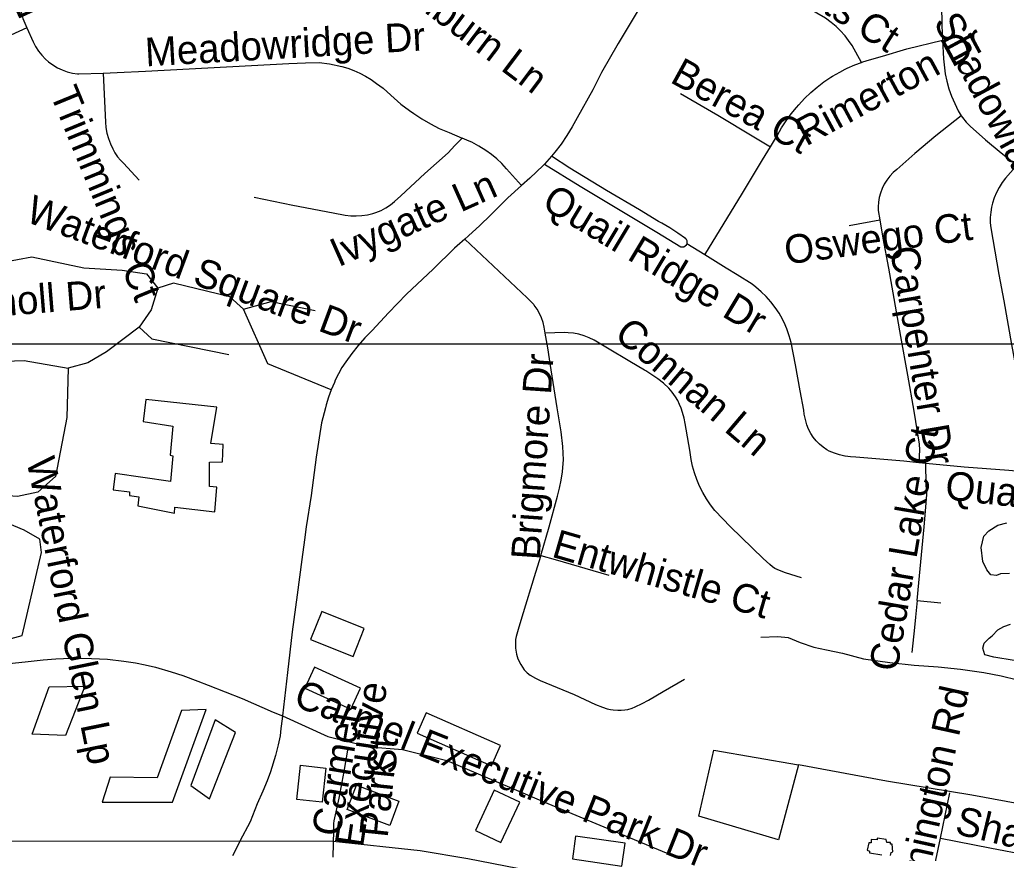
# Model space of a CAD drawing. Extents: x 1383679 to 1536984, y 460658 to 651027.
# Drawn here: x 1447333 to 1450610, y 491982 to 494749 of the extents above; entities that cross this region are included whole.
import ezdxf

# ---------------------------------------------------------------- set-up
doc = ezdxf.new("R2010")
doc.units = 0
for name, color, linetype in [('Exist Cultural Warehouse Building Footprint', 7, 'Continuous'), ('Exist Hydrographic Misc Water Feature', 7, 'Continuous'), ('Exist Road Non-System Type 51', 7, 'Continuous'), ('Exist Road Non-System Type 51 Label', 7, 'Continuous'), ('Exist Road Primary NC UnDivided 4 Lane Attributed', 7, 'Continuous'), ('Exist Utilities Electrical Transmission Line', 7, 'Continuous'), ('Map Preparation Inset Cut Line', 7, 'Continuous')]:
    doc.layers.add(name, color=color, linetype=linetype)

msp = doc.modelspace()

# ---------------------------------------------------------------- linework, layer by layer
at = {"layer": 'Exist Cultural Warehouse Building Footprint'}
for points in [[(1447752.1, 493487.8), (1447742.5, 493414.9), (1447841.8, 493399.4), (1447832.2, 493303.1), (1447841.8, 493301.5), (1447833.8, 493216.2), (1447649.7, 493242.6), (1447643.3, 493188.2), (1447697.7, 493182), (1447697.7, 493169.6), (1447728.1, 493164.9), (1447724.9, 493135.4), (1447846.6, 493110.6), (1447848.2, 493130.8), (1447981, 493115.2), (1447987.4, 493197.5), (1447963.4, 493199.1), (1447963.4, 493279.8), (1448006.6, 493281.4), (1448008.2, 493338.8), (1447968.2, 493341.9), (1447987.4, 493463), (1447752.1, 493487.8)], [(1448336.3, 492784.6), (1448299.3, 492691.6), (1448440.3, 492635.5), (1448477.3, 492728.5), (1448336.3, 492784.6)], [(1448312.3, 492599.8), (1448280.2, 492529.8), (1448432.3, 492460.1), (1448464.4, 492530.1), (1448312.3, 492599.8)], [(1447430.4, 492533.8), (1447548.9, 492536.9), (1447484.9, 492372.4), (1447374.4, 492377), (1447430.4, 492533.8)], [(1447633.7, 492234.2), (1447606.5, 492151.9), (1447840.2, 492151.9), (1447952.2, 492459.3), (1447870.6, 492456.2), (1447788.9, 492232.6), (1447633.7, 492234.2)], [(1448683.6, 492448.4), (1448653.5, 492380.2), (1448899.7, 492271.5), (1448929.8, 492339.7), (1448683.6, 492448.4)], [(1447982.6, 492425.2), (1447901, 492206.2), (1447963.4, 492162.8), (1448049.8, 492383.2), (1447982.6, 492425.2)], [(1448265.9, 492273.8), (1448350.1, 492264.7), (1448337.9, 492151.1), (1448253.6, 492160.2), (1448265.9, 492273.8)], [(1448592.4, 492155), (1448562.1, 492074.2), (1448421.1, 492127.1), (1448451.4, 492207.9), (1448592.4, 492155)], [(1448846.8, 492057.2), (1448931.5, 492017.7), (1448994.1, 492151.9), (1448909.4, 492191.4), (1448846.8, 492057.2)], [(1449179.7, 492038.6), (1449168.9, 491962.9), (1449333.4, 491939.2), (1449344.3, 492014.9), (1449179.7, 492038.6)], [(1450161.1, 492027.9), (1450162.1, 492016), (1450153.9, 492016), (1450148.8, 491992.2), (1450156, 491989.2), (1450156, 491983.2), (1450196.9, 491976.3)], [(1450225.5, 491974.3), (1450227.5, 491984.2), (1450233.7, 491986.2), (1450231.6, 492012), (1450225.5, 492012), (1450225.5, 492017.9), (1450213.2, 492017.9), (1450211.2, 492027.9), (1450181.5, 492031.8), (1450181.5, 492025.9), (1450161.1, 492027.9)]]:
    msp.add_lwpolyline(points, dxfattribs=at)
at = {"layer": 'Exist Hydrographic Misc Water Feature'}
for points in [[(1450621.7, 492911.1), (1450591.8, 492909.2), (1450577.6, 492903.8), (1450559.6, 492905.8), (1450545.9, 492922.4), (1450532.4, 492950.6), (1450527.3, 492996.7), (1450536, 493034.3), (1450552.3, 493052), (1450582.6, 493071.1), (1450612.8, 493078.7)], [(1450704.3, 492610.7), (1450568.6, 492633.2), (1450538.7, 492640.3), (1450533.1, 492662.6), (1450537.4, 492679.8), (1450553.8, 492695.8), (1450563.9, 492703.8), (1450582.2, 492723.1), (1450602.4, 492735.1), (1450624.7, 492742.8)], [(1449795.5, 492699.6), (1449851.5, 492700.9), (1449885.4, 492697.8), (1449925.2, 492681.4), (1449971, 492666.5), (1450012.9, 492657.5), (1450066.7, 492646.5), (1450136.3, 492627.1), (1450224.1, 492615.5), (1450304.1, 492606.5), (1450383.9, 492600.8), (1450457.9, 492593.5), (1450535.7, 492582.1), (1450593.5, 492571.1), (1450647.3, 492557.7), (1450703, 492542.6)]]:
    msp.add_lwpolyline(points, dxfattribs=at)
at = {"layer": 'Exist Road Non-System Type 51'}
for p, q in [((1449099.6, 494296.2), (1449076.3, 494270)), ((1450089, 494065.6), (1450190.4, 494084.8)), ((1449608.8, 493968.2), (1449549.4, 494005)), ((1450343, 493276.3), (1450319.5, 493278.5)), ((1450314.4, 492821), (1450392.7, 492813.5)), ((1450392, 492032.4), (1450423.4, 492182.8)), ((1448098.2, 492085.7), (1448064.5, 492021.5)), ((1448064.5, 492021.5), (1448050.4, 491994.5)), ((1450365.6, 491906.1), (1450392, 492032.4)), ((1448050.4, 491994.5), (1448039.3, 491973.3))]:
    msp.add_line(p, q, dxfattribs=at)
for points in [[(1447447, 495029.8), (1447430.6, 495001.9), (1447397.6, 494952.2), (1447356, 494884.3), (1447348.4, 494870.7), (1447342.1, 494855.8), (1447337.5, 494840.3), (1447334.6, 494824.3), (1447333.5, 494808.2), (1447334.1, 494792.3), (1447335.1, 494784.2), (1447342.8, 494753.8), (1447356.7, 494722.8)], [(1450128.9, 494607.2), (1450098.1, 494663.3), (1450086.6, 494680.7), (1450075, 494695.8), (1450074, 494697.2), (1450060.1, 494712.6), (1450045, 494727), (1450028.9, 494740.2), (1450009.5, 494753.9), (1449989.2, 494766.3), (1449987, 494767.6), (1449919.7, 494807.5), (1449857, 494844.9), (1449759.9, 494904)], [(1450385, 494889.7), (1450389.1, 494871), (1450392.8, 494847.4), (1450394.9, 494823.5), (1450395.4, 494799.6), (1450396.4, 494729.7), (1450398.6, 494681.4)], [(1449408.7, 494816.6), (1449400.6, 494802.9), (1449320.9, 494670.4), (1449265.1, 494573.9), (1449236.3, 494516.5), (1449184.6, 494423.7), (1449168.1, 494393.8), (1449150.3, 494364.8), (1449131.1, 494336.5), (1449110.6, 494309.2), (1449105.5, 494302.8), (1449099.6, 494296.2)], [(1447356.7, 494722.8), (1447234.1, 494666.5), (1447170.4, 494638), (1447025.9, 494572.3)], [(1447356.7, 494722.8), (1447377.7, 494675.6), (1447385.7, 494660.1), (1447395.3, 494645), (1447406.4, 494631), (1447418.7, 494618.3), (1447428.5, 494609.6), (1447442.7, 494599.1), (1447457.9, 494590), (1447473.9, 494582.4), (1447490.6, 494576.4), (1447507.9, 494572), (1447525.1, 494569.4), (1447529, 494569), (1447609.7, 494572)], [(1450128.9, 494607.2), (1450133.6, 494608.9), (1450156.5, 494616.1), (1450199, 494628), (1450280, 494652.1), (1450398.6, 494681.4)], [(1450398.6, 494681.4), (1450401.4, 494619.8), (1450407.3, 494569.6), (1450412.7, 494545.5), (1450420.1, 494520), (1450428.9, 494495.1), (1450439.2, 494470.7), (1450450.9, 494447), (1450461.1, 494430.4)], [(1447609.7, 494572), (1447656.7, 494573.6), (1447750.4, 494578.9), (1448102.4, 494597), (1448227, 494603.6), (1448282, 494606.5), (1448327.1, 494607.1), (1448361.7, 494602.8), (1448403, 494593.5), (1448422.4, 494588.1), (1448442.9, 494580.9), (1448462.9, 494572.2), (1448482.1, 494562), (1448500.6, 494550.6), (1448518.2, 494537.7), (1448540.1, 494521.8), (1448565.9, 494498.2), (1448598.5, 494468.8), (1448627.2, 494447.8), (1448641.6, 494437.8), (1448669.2, 494420), (1448697.6, 494403.6), (1448726.7, 494388.5), (1448759, 494375.2), (1448803, 494356.4)], [(1449826.9, 494327.6), (1449849.9, 494365.5), (1449863.8, 494390), (1449879.2, 494413.6), (1449895.8, 494436.4), (1449913.7, 494458.2), (1449921.4, 494466.9), (1449940.6, 494487.6), (1449960.9, 494507.1), (1449982.3, 494525.4), (1450004.7, 494542.5), (1450028, 494558.4), (1450033.1, 494561.6), (1450057.2, 494575.6), (1450075, 494584.6), (1450082, 494588.1), (1450107.5, 494599.3), (1450128.9, 494607.2)], [(1447609.7, 494572), (1447617.6, 494409.6), (1447619.3, 494391.1), (1447622.6, 494372.8), (1447627.4, 494354.8), (1447633.8, 494337.3), (1447641.6, 494320.5), (1447649.1, 494307), (1447657.9, 494294.4), (1447668, 494282.7), (1447677.9, 494273.2), (1447730.1, 494216.9)], [(1449528.4, 494504.6), (1449651.8, 494432.1), (1449771.7, 494360.1), (1449826.9, 494327.6)], [(1450461.1, 494430.4), (1450376.2, 494363.9), (1450306.9, 494304.5), (1450246.3, 494252.2), (1450234.2, 494241.5), (1450223.2, 494229.7), (1450213.4, 494216.9), (1450204.9, 494203.1), (1450197.8, 494188.7), (1450192.1, 494173.5), (1450188.2, 494158.6), (1450185.7, 494143.4), (1450184.8, 494128), (1450185.3, 494115.4), (1450190.4, 494084.8)], [(1450461.1, 494430.4), (1450464.9, 494424.3), (1450477.3, 494409.3), (1450490.7, 494396.1), (1450541.2, 494350.5), (1450593.5, 494306.8), (1450646, 494266.1)], [(1448111.9, 494160.3), (1448240.2, 494133.9), (1448374.3, 494108.5), (1448414.2, 494100.7), (1448432.6, 494098.5), (1448451, 494097.9), (1448469.5, 494098.9), (1448487.8, 494101.5), (1448505.8, 494105.6), (1448516.3, 494108.7), (1448533.2, 494116.1), (1448549.4, 494124.9), (1448564.7, 494135), (1448578, 494145.4), (1448599, 494164.5), (1448679.1, 494238.2), (1448756.2, 494307.6), (1448778.5, 494331.5), (1448803, 494356.4)], [(1449000.2, 494199), (1448949.9, 494254.5), (1448934.4, 494271.3), (1448917.8, 494287.1), (1448900.2, 494301.7), (1448881.7, 494315), (1448858.4, 494329.4), (1448834.3, 494342.5), (1448826.4, 494346.4), (1448803, 494356.4)], [(1449608.8, 493968.2), (1449734.1, 494173.5), (1449800.7, 494284.5), (1449826.9, 494327.6)], [(1449076.3, 494270), (1449071.7, 494264.9), (1449027.5, 494223.7), (1449000.2, 494199)], [(1449076.3, 494270), (1449194.9, 494196.2), (1449338.7, 494110.5), (1449449.2, 494044.1), (1449529.7, 493995.7), (1449534.7, 493994.9), (1449539.6, 493995.7), (1449544.1, 493998), (1449547.7, 494001.6), (1449549.4, 494005)], [(1449549.4, 494005), (1449550, 494006.1), (1449550.8, 494011), (1449550.3, 494015.4), (1449548.2, 494019.3), (1449544.9, 494022.2), (1449544.6, 494022.4), (1449519.3, 494040.8), (1449493.1, 494057.9), (1449466, 494073.6), (1449455, 494079.5), (1449391.5, 494117.5), (1449282.3, 494182.7), (1449160.9, 494256.8), (1449099.6, 494296.2)], [(1450646, 494266.1), (1450641.4, 494260.9), (1450608.4, 494223.3), (1450596.8, 494208.3), (1450586.5, 494192.3), (1450577.7, 494175.4), (1450570.4, 494157.8), (1450564.7, 494139.7), (1450561.6, 494126.8), (1450558.6, 494109.9), (1450557.2, 494092.5), (1450557.4, 494075.1), (1450559.3, 494058.6), (1450586.1, 493902.9), (1450602.3, 493815.4), (1450627.4, 493671.3), (1450656.4, 493515.3), (1450678.4, 493387.1), (1450694.5, 493291.2), (1450693.3, 493245.4)], [(1449000.2, 494199), (1448954.8, 494158), (1448896.7, 494100.8), (1448861, 494065.6), (1448824.1, 494031.5), (1448811.9, 494020.9)], [(1450190.4, 494084.8), (1450200.5, 494024.4), (1450219, 493924.4), (1450259.1, 493697.6), (1450281.8, 493569.5), (1450303.5, 493449.9), (1450321.3, 493340), (1450322, 493321.2), (1450319.5, 493278.5)], [(1448811.9, 494020.9), (1448786.2, 493998.6), (1448776.8, 493990.8), (1448706.1, 493921.3), (1448618.3, 493837.5), (1448558.1, 493776.4), (1448503.2, 493717.3), (1448479.8, 493693), (1448457.5, 493667.6), (1448436.4, 493641.2), (1448416.6, 493613.8), (1448403.4, 493594), (1448391.6, 493573.4), (1448381.2, 493552.1), (1448378.2, 493545.2), (1448367.7, 493520.9), (1448358.6, 493496), (1448351.1, 493470.7), (1448348.5, 493460.5), (1448335.9, 493410.9), (1448317.9, 493296.4), (1448301.4, 493169.3), (1448284.8, 493066), (1448279.3, 493022.4), (1448270.1, 492957.1), (1448254.5, 492839.4), (1448238.4, 492717), (1448222.7, 492581.8), (1448205.5, 492437.8)], [(1449078.9, 493708.2), (1449075.5, 493727.9), (1449071.8, 493743.9), (1449066.6, 493759.4), (1449059.9, 493774.3), (1449051.8, 493788.5), (1449042.4, 493801.9), (1449040.6, 493804.2), (1449018.5, 493826.2), (1448811.9, 494020.9)], [(1447077.7, 493562.8), (1447077.7, 493642.1), (1447077.7, 493681.8), (1447137.2, 493828.2), (1447229, 493934.9), (1447372.7, 493962.1), (1447546.3, 493924.9), (1447672.7, 493917.5), (1447754.5, 493905.1), (1447791.7, 493858)], [(1450319.5, 493278.5), (1450270.3, 493283.2), (1450111.1, 493297.1), (1450092.8, 493298), (1450075, 493300.5), (1450074.6, 493300.5), (1450056.7, 493304.6), (1450039.3, 493310.1), (1450022.3, 493317.2), (1450014.7, 493321), (1450001.7, 493329.6), (1449989.7, 493339.6), (1449978.8, 493350.7), (1449969, 493362.8), (1449960.6, 493375.9), (1449953.4, 493389.8), (1449947.8, 493404.3), (1449942.9, 493421.6), (1449939.5, 493439.4), (1449938, 493452.5), (1449926.1, 493517.5), (1449909.8, 493603.5), (1449896.1, 493677.3), (1449889.6, 493700.2), (1449881.6, 493722.5), (1449872.2, 493744.3), (1449861.4, 493765.4), (1449855.8, 493775), (1449842.8, 493794.3), (1449828.5, 493812.6), (1449813, 493829.9), (1449796.3, 493846.2), (1449778.6, 493861.2), (1449766, 493870.8), (1449716.9, 493901.9), (1449679.4, 493924.6), (1449608.8, 493968.2)], [(1447843.9, 493874.7), (1447791.7, 493858), (1447769.4, 493786), (1447729.7, 493729), (1447771.9, 493689.3), (1448027.2, 493637.2)], [(1448076.6, 493788.6), (1448031.1, 493829.1), (1447843.9, 493874.7)], [(1448367.7, 493520.9), (1448157.5, 493606.4), (1448076.6, 493788.6), (1448167.7, 493813.9), (1448314.4, 493783.6)], [(1447729.7, 493729), (1447620.7, 493647.1), (1447558.7, 493609.9), (1447494.2, 493592.5), (1447489.3, 493428.8), (1447452.1, 493232.8), (1447392.6, 493180.8), (1447325.6, 493165.9), (1447263.7, 493170.8), (1447194.3, 493195.6), (1447095.1, 493252.7), (1447067.8, 493337), (1447100, 493399), (1447077.7, 493562.8), (1447251.3, 493614.9), (1447348, 493617.3), (1447494.2, 493592.5)], [(1449063.9, 492970.8), (1449092.1, 493066), (1449119, 493167), (1449126.2, 493193.8), (1449131.9, 493221), (1449136.1, 493248.5), (1449138.7, 493276.2), (1449139.4, 493288.4), (1449137.7, 493332.6), (1449131.1, 493381), (1449118.7, 493461.1), (1449098.9, 493586.8), (1449087, 493659.9), (1449078.9, 493708.2)], [(1449930.3, 492895.8), (1449877.5, 492913.3), (1449857.4, 492920.4), (1449849.5, 492923.6), (1449841.6, 492927.4), (1449833.8, 492932.6), (1449824.4, 492940.3), (1449802.5, 492960.3), (1449693.8, 493066), (1449642.7, 493119.9), (1449627.9, 493138.7), (1449614.4, 493158.5), (1449602.2, 493179.1), (1449591.4, 493200.5), (1449582, 493222.6), (1449574.4, 493244.5), (1449568.2, 493266.9), (1449563.6, 493289.6), (1449560.5, 493312.6), (1449560.4, 493313.3), (1449547.2, 493389.8), (1449543.4, 493408.5), (1449539.9, 493426.6), (1449535, 493445.3), (1449529.9, 493459.6), (1449525.3, 493472), (1449518.8, 493485.4), (1449511.1, 493497.1), (1449500.1, 493512.7), (1449489, 493526.1), (1449471.5, 493542.2), (1449452.9, 493557.2), (1449432.7, 493570.5), (1449413.1, 493583.1), (1449408.8, 493585.5), (1449360.2, 493614.7), (1449285.3, 493659.2), (1449241.5, 493685.5), (1449225.1, 493693.4), (1449208.1, 493699.8), (1449190.6, 493704.7), (1449172.8, 493708.1), (1449154.7, 493709.9), (1449142.4, 493710.3), (1449078.9, 493708.2)], [(1450314.4, 492821), (1450319.6, 492879.2), (1450337.4, 493066), (1450341.6, 493117.6), (1450346.2, 493173), (1450344.7, 493206.4), (1450343, 493276.3)], [(1450693.3, 493245.4), (1450619, 493252.1), (1450470.4, 493264.1), (1450343, 493276.3)], [(1446713.3, 492895.5), (1446767.9, 492840.9), (1446810, 492793.8), (1446847.2, 492766.5), (1447033.1, 492699.5), (1447258.7, 492682.2), (1447340.5, 492704.5), (1447405, 492979.8), (1447400, 493024.5), (1447348, 493054.2), (1447050.5, 493178.3)], [(1449063.9, 492970.8), (1449046.8, 492913.4), (1449001.3, 492765.5), (1448988.9, 492725.2), (1448982.3, 492701.4), (1448980.4, 492691.7), (1448979.6, 492682.6), (1448979.4, 492671.9), (1448979.8, 492662.2), (1448982.9, 492643.3), (1448985.2, 492634.7), (1448987.6, 492627.3), (1448997.4, 492608.3), (1449002.7, 492599.6), (1449009.1, 492590.9), (1449018.6, 492581.2), (1449029, 492572.8), (1449045.9, 492562.6), (1449061.4, 492555.4), (1449175.1, 492508.5), (1449246.1, 492475.8), (1449268.9, 492466.4), (1449284.2, 492461.2), (1449295.7, 492458.6), (1449304, 492457.5), (1449319.7, 492456.5), (1449331.3, 492456.7), (1449343.5, 492457.7), (1449352.8, 492459.4), (1449367.2, 492463.5), (1449377.5, 492467.5), (1449401.1, 492478.6), (1449421.8, 492490.3), (1449470.7, 492519.3), (1449541.2, 492560.3)], [(1449063.9, 492970.8), (1449111.3, 492957.1), (1449290.4, 492905.5)], [(1450314.4, 492821), (1450309.4, 492765.7), (1450305.9, 492731.6), (1450296.9, 492648.3)], [(1447218.6, 492606), (1447250, 492607.5), (1447308.4, 492612.4), (1447360.5, 492618.5), (1447410.2, 492624), (1447453.2, 492627.6), (1447503.9, 492629.6), (1447570.8, 492628.6), (1447623.9, 492626.1), (1447679, 492620), (1447717, 492613.9), (1447749.4, 492607.3), (1447783.9, 492599.2), (1447835.9, 492584.4), (1447875.2, 492571.6), (1447924.7, 492553.3), (1447958.5, 492540.4), (1448071.9, 492495.1), (1448174.3, 492450.4), (1448205.5, 492437.8)], [(1448205.5, 492437.8), (1448204.3, 492428.2), (1448200.8, 492395.8), (1448197.5, 492371.2), (1448191.4, 492341.3), (1448182.7, 492306.8), (1448165.8, 492252), (1448154.9, 492222), (1448140.7, 492187.9), (1448122, 492145.4), (1448098.2, 492085.7)], [(1448205.5, 492437.8), (1448355.9, 492369.6), (1448495.1, 492334.7), (1448604.9, 492326.7), (1448752.2, 492289.2), (1449086.9, 492147.2), (1449480.5, 491983.7)], [(1448421.8, 492323.7), (1448409.5, 492253.6), (1448392.5, 492165.1), (1448376.7, 492089.4)], [(1448376.7, 492089.4), (1448375.2, 492080.9), (1448375.2, 492057.9), (1448372.9, 491968.6)], [(1450392, 492032.4), (1450555.6, 492000.3), (1450810.9, 491951.3), (1450838, 491946), (1450864.2, 491939.9), (1450891.5, 491932.2)]]:
    msp.add_lwpolyline(points, dxfattribs=at)
at = {"layer": 'Exist Road Primary NC UnDivided 4 Lane Attributed'}
msp.add_lwpolyline([(1451375.5, 491065.7), (1451176.9, 491273.3), (1451016.4, 491407.7), (1450878.3, 491495), (1450727.6, 491571.2), (1450522.5, 491631.9), (1448821.1, 491963.1), (1448663.7, 491989.9), (1448374.3, 492021.1), (1446210.8, 492023.2), (1445181.3, 492024.4), (1443311.1, 492026.6), (1442943.4, 492033), (1442758.7, 492046.1), (1442516.1, 492090.9), (1442320.7, 492135.6), (1441928.9, 492271.9), (1440818.3, 492661.4), (1440612.8, 492709), (1440461.4, 492729.2)], dxfattribs=at)
at = {"layer": 'Exist Utilities Electrical Transmission Line'}
for points in [[(1449919.8, 492274.9), (1449853.3, 492025.9), (1449588.6, 492104.9), (1449638.6, 492324), (1449919.8, 492274.9)], [(1452109.5, 491876.9), (1451714.7, 491954), (1451138.3, 492056.5), (1450496.2, 492174.2), (1450213, 492221.6), (1449919.8, 492274.9)]]:
    msp.add_lwpolyline(points, dxfattribs=at)
at = {"layer": 'Map Preparation Inset Cut Line'}
for points in [[(1446195.4, 477316), (1383679.3, 477316), (1383679.3, 520758.2), (1458567.8, 520758.2), (1458567.8, 493672.2), (1446195.4, 493672.2), (1446195.4, 477316)], [(1446195.4, 477316), (1480703, 477316), (1498974.3, 494868.2), (1521133.6, 516155.5), (1521133.6, 520758.2), (1458567.8, 520758.2), (1458567.8, 493672.2), (1446195.4, 493672.2), (1446195.4, 477316)]]:
    msp.add_lwpolyline(points, dxfattribs=at)

# ---------------------------------------------------------------- texts
at = {"layer": 'Exist Road Non-System Type 51 Label'}
for s, rotation, p in [('Winburn Ln', 322.9439, (1448521.6, 494890.5)), ('Dotts Ct', 327.8048, (1449827.7, 494882)), ('All Saints Ln', 24.6921, (1446808.7, 494513.3)), ('Shadowlake Dr', 298.2732, (1450367.1, 494741.5)), ('Meadowridge Dr', 3.29, (1447751.8, 494594.1)), ('Rimerton Dr', 28.4179, (1449945.1, 494327.7)), ('Berea Ct', 331.1898, (1449489.8, 494543.3)), ('Trimmings Ct', 292.3286, (1447431.8, 494504.6)), ('Ivygate Ln', 24.1216, (1448391.7, 493927)), ('Quail Ridge Dr', 329.0368, (1449062.7, 494126.6)), ('Waterford Square Dr', 339.5696, (1447347.6, 494080.4)), ('Oswego Ct', 7.5652, (1449879.7, 493936.5)), ('Carpenter Dr', 279.6597, (1450223.7, 493989.8)), ('Waterford Knoll Dr', 4.6784, (1446581.7, 493708.2)), ('Connan Ln', 319.6558, (1449303.5, 493696.6)), ('Brigmore Dr', 86.0816, (1449059.9, 492953.7)), ('Cedar Lake Ct', 80.3415, (1450247.7, 492581.8)), ('Waterford Glen Lp', 281.5295, (1447354.7, 493286.7)), ('Quail Ridge Dr', 353.5964, (1450404.3, 493157.5)), ('Entwhistle Ct', 343.8115, (1449096.5, 492967)), ('Carmel Executive Park Dr', 338.2518, (1448237.6, 492473.7)), ('Executive', 81.4691, (1448472.8, 491998.6)), ('Bannington Rd', 77.6045, (1450307.1, 491703.5)), ('Carmel', 80.311, (1448395.8, 492033.6)), ('St', 85.914, (1448580.8, 492243)), ('Park', 84.0936, (1448555, 492031.4)), ('Shannon Willow Rd', 346.4528, (1450436.1, 492047.4))]:
    msp.add_text(s, height=95, rotation=rotation, dxfattribs=at).set_placement(p)

doc.saveas('drawing.dxf')
